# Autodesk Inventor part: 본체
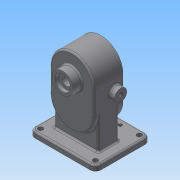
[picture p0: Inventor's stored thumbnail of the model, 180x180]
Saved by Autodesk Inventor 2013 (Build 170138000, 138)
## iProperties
Created: 2020-09
Part Number: 본체
Material: Generic
Document SubType Name: Modeling
Designer: Administrator
Density: 1 g/cm^3
Author: Administrator
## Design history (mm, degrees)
sketch "스케치1"
  geometry: L1 (-50, -60)-(50, -60); L2 (50, -60)-(50, 60); L3 (50, 60)-(-50, 60); L4 (-50, 60)-(-50, -60); L5 (-50, -60)-(50, 60); L6 (50, -60)-(-50, 60); 1 further point
  constraints: 12 end point, 2 midpoint, 2 parallel, 1 horizontal, 1 perpendicular
  dimensions: "d0" = 100 distance of L1.start L1.end; "d2" = 120 distance of L1.end L2.end
extrude "돌출1" new body sketch "스케치1" distance "d3" = 10; taper "d4" = 0 deg
sketch "스케치2"
  geometry: L1 (-40, 112)-(-40, 68); L2 (40, 112)-(40, 68); L3 (60, 0)-(-60, 0) reference; A1 r 40 centre (0, 112) between (40, 112) and (-40, 112); A2 r 40 centre (0, 68) between (-40, 68) and (40, 68); 2 further points
  constraints: 4 end point, 4 point on circle, 4 tangent, 2 centre point, 2 vertical alignment, 1 equal radius, 1 midpoint
  dimensions: "d5" = 80 diameter of A1; "d7" = 44 distance of A2.centre A1.centre; "d8" = 112 distance from line of L3 A1.centre
extrude "돌출2" join sketch "스케치2" distance "d9" = 20; taper "d11" = 0 deg; dims "d10" = 33, "d12" = 0
sketch "스케치3"
  geometry: C1 r 19 at (112, 0); A1 r 40 centre (112, 0) between (112, -40) and (112, 40) reference; 1 further point
  constraints: 1 centre point, 1 coincident
  dimensions: "d13" = 38 diameter of C1
extrude "돌출3" join sketch "스케치3" distance "d15" = 17; taper "d16" = 0 deg
sketch "스케치4"
  geometry: L1 (-112, -24)-(-68, -24); L2 (-112, 24)-(-68, 24); A1 r 40 centre (-112, 0) between (-112, 40) and (-112, -40) reference; A2 r 40 centre (-68, 0) between (-68, -40) and (-68, 40) reference; A3 r 24 centre (-112, 0) between (-112, -24) and (-112, 24); A4 r 24 centre (-68, 0) between (-68, -24) and (-68, 24); 1 further point
  constraints: 4 end point, 4 point on circle, 4 tangent, 2 centre point, 2 coincident, 1 equal radius
  dimensions: "d17" = 48 diameter of A3
extrude "돌출4" cut sketch "스케치4" distance "d19" = 29; taper "d20" = 0 deg
sketch "스케치5"
  geometry: C1 r 19 at (0, 0) reference; C2 r 14 at (0, 0); 1 further point
  constraints: 1 centre point, 1 coincident
  dimensions: "d21" = 28 diameter of C2
extrude "돌출5" cut sketch "스케치5" distance "d23" = 7.3; taper "d24" = 0 deg
sketch "스케치6"
  geometry: C1 r 12.5 at (-112, 0); A1 r 24 centre (-112, 0) between (-112, 24) and (-112, -24) reference; 1 further point
  constraints: 1 centre point, 1 coincident
  dimensions: "d25" = 25 diameter of C1
extrude "돌출6" cut sketch "스케치6" distance "d27" = 15; taper "d28" = 0 deg
sketch "스케치7"
  geometry: C1 r 14 at (0, 0) reference; C2 r 8.5 at (0, 0); 1 further point
  constraints: 1 centre point, 1 coincident
  dimensions: "d29" = 17 diameter of C2
extrude "돌출7" cut sketch "스케치7" stored distance "d31" = 15; taper "d32" = 0 deg
sketch "스케치8"
  geometry: C1 r 12.5 at (-68, 0); A1 r 24 centre (-68, 0) between (-68, -24) and (-68, 24) reference; 1 further point
  constraints: 1 centre point, 1 coincident
  dimensions: "d33" = 25 diameter of C1
extrude "돌출8" cut sketch "스케치8" distance "d35" = 15; taper "d36" = 0 deg
sketch "스케치9"
  geometry: L1 (-25, -40)-(12, -40); L2 (12, -40)-(12, 40); L3 (12, 40)-(-25, 40); L4 (-25, 40)-(-25, -40); L5 (-50, 60)-(-50, -60) reference; 2 further points
  constraints: 8 end point, 2 parallel, 1 horizontal, 1 horizontal alignment, 1 midpoint, 1 perpendicular
  dimensions: "d37" = 25 distance between parallel lines of L4 L5; "d38" = 37 distance of L2.end L3.end; "d39" = 80 distance of L1.end L2.end
extrude "돌출9" join sketch "스케치9" stored distance "d40" = 15; taper "d41" = 0 deg
fillet "모깎기1" dims "d42" = 3
fillet "모깎기2" dims "d43" = 10
fillet "모깎기3" dims "d44" = 3
fillet "모깎기4" dims "d45" = 3
fillet "모깎기5" dims "d46" = 3
fillet "모깎기6" dims "d47" = 3
fillet "모깎기7" dims "d48" = 3
chamfer "모따기1" distance "d49" = 0.7; stored, may be unused: second distance "d50" = 2, angle "d51" = 30 deg
chamfer "모따기2" distance "d52" = 1; stored, may be unused: second distance "d53" = 2, angle "d54" = 45 deg
chamfer "모따기3" distance "d55" = 1; stored, may be unused: second distance "d56" = 2, angle "d57" = 45 deg
sketch "스케치10"
  geometry: L1 (-50, 44)-(0, 44) reference; L2 (-60, -68)-(20, -68) reference; L3 (0, 44)-(0, 0) reference; C1 r 11 at (-14, 22); 2 further points
  constraints: 1 centre point, 1 midpoint
  dimensions: "d58" = 22 diameter of C1; "d92" = 22 distance from line of L1 C1.centre; "d93" = 14 distance from line of L3 C1.centre
extrude "돌출10" join sketch "스케치10" distance "d60" = 10; taper "d61" = 0 deg
sketch "스케치11"
  geometry: C1 r 11 at (0, 0) reference; 1 further point
hole "구멍1" sketch "스케치11" at (0, 0) diameter "d62" = 8.376; stored, may be unused: countersink angle "d66" = 90 deg, drill point angle "d68" = 0 deg; dims "d63" = 100, "d64" = 4, "d65" = 2, "d67" = 8
fillet "모깎기8" dims "d69" = 3
sketch "스케치12"
  geometry: A1 r 40 centre (-112, 0) between (-112, 40) and (-112, -40) reference; A2 r 40 centre (-68, 0) between (-68, -40) and (-68, 40) reference; A3 r 31 centre (-112, 0) between (-143, 0) and (-112, 31); A4 r 31 centre (-68, 0) between (-37, 0) and (-68, -31); 3 further points
  constraints: 6 point on circle, 2 centre point, 2 coincident
  dimensions: "d70" = 62 diameter of A3; "d72" = 62 diameter of A4
hole "구멍2" sketch "스케치12" at (-143, 0), (-37, 0), (-68, -31), (-68, 31), (-112, 31), (-112, -31) diameter "d73" = 4.134; stored, may be unused: countersink angle "d77" = 90 deg, drill point angle "d79" = 118 deg; dims "d74" = 10, "d75" = 4, "d76" = 2, "d78" = 12
fillet "모깎기9" dims "d80" = 3
sketch "스케치13"
  geometry: A1 r 10 centre (-40, -50) between (-50, -50) and (-40, -60) reference; A2 r 10 centre (-40, 50) between (-40, 60) and (-50, 50) reference; A3 r 10 centre (40, -50) between (40, -60) and (50, -50) reference; A4 r 10 centre (40, 50) between (50, 50) and (40, 60) reference; 1 further point
hole "구멍3" sketch "스케치13" at (-40, -50), (-40, 50), (40, 50), (40, -50) diameter "d81" = 9; stored, may be unused: countersink angle "d85" = 90 deg, drill point angle "d87" = 118 deg; dims "d82" = 10, "d83" = 4, "d84" = 2, "d86" = 12
sketch "스케치14"
  geometry: L1 (50, -50)-(50, 50) reference; L2 (-40, -60)-(40, -60) reference; 2 further points
  constraints: 1 other
  dimensions: "d88" = 12 distance from line of L1 point (38, 0); "d89" = 60 distance from line of L2 point (38, 0)
feature "엠보싱1" sketch "스케치14" dims "d0" = 100, "d2" = 120, "d90" = 0.5, "d91" = 0
fillet "모깎기10" dims "d94" = 0.5
node "솔리드1"
mirror "대칭1"
